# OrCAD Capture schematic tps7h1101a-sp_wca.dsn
size Custom; title: TPS7H1101A-SP 1.5-V to 7-V Input, 3-A; rev: C; note: Datasheet: SLVSDW6C   EVM User Guide: SLVU944B; note: Radiation-Hardened LDO Regulator
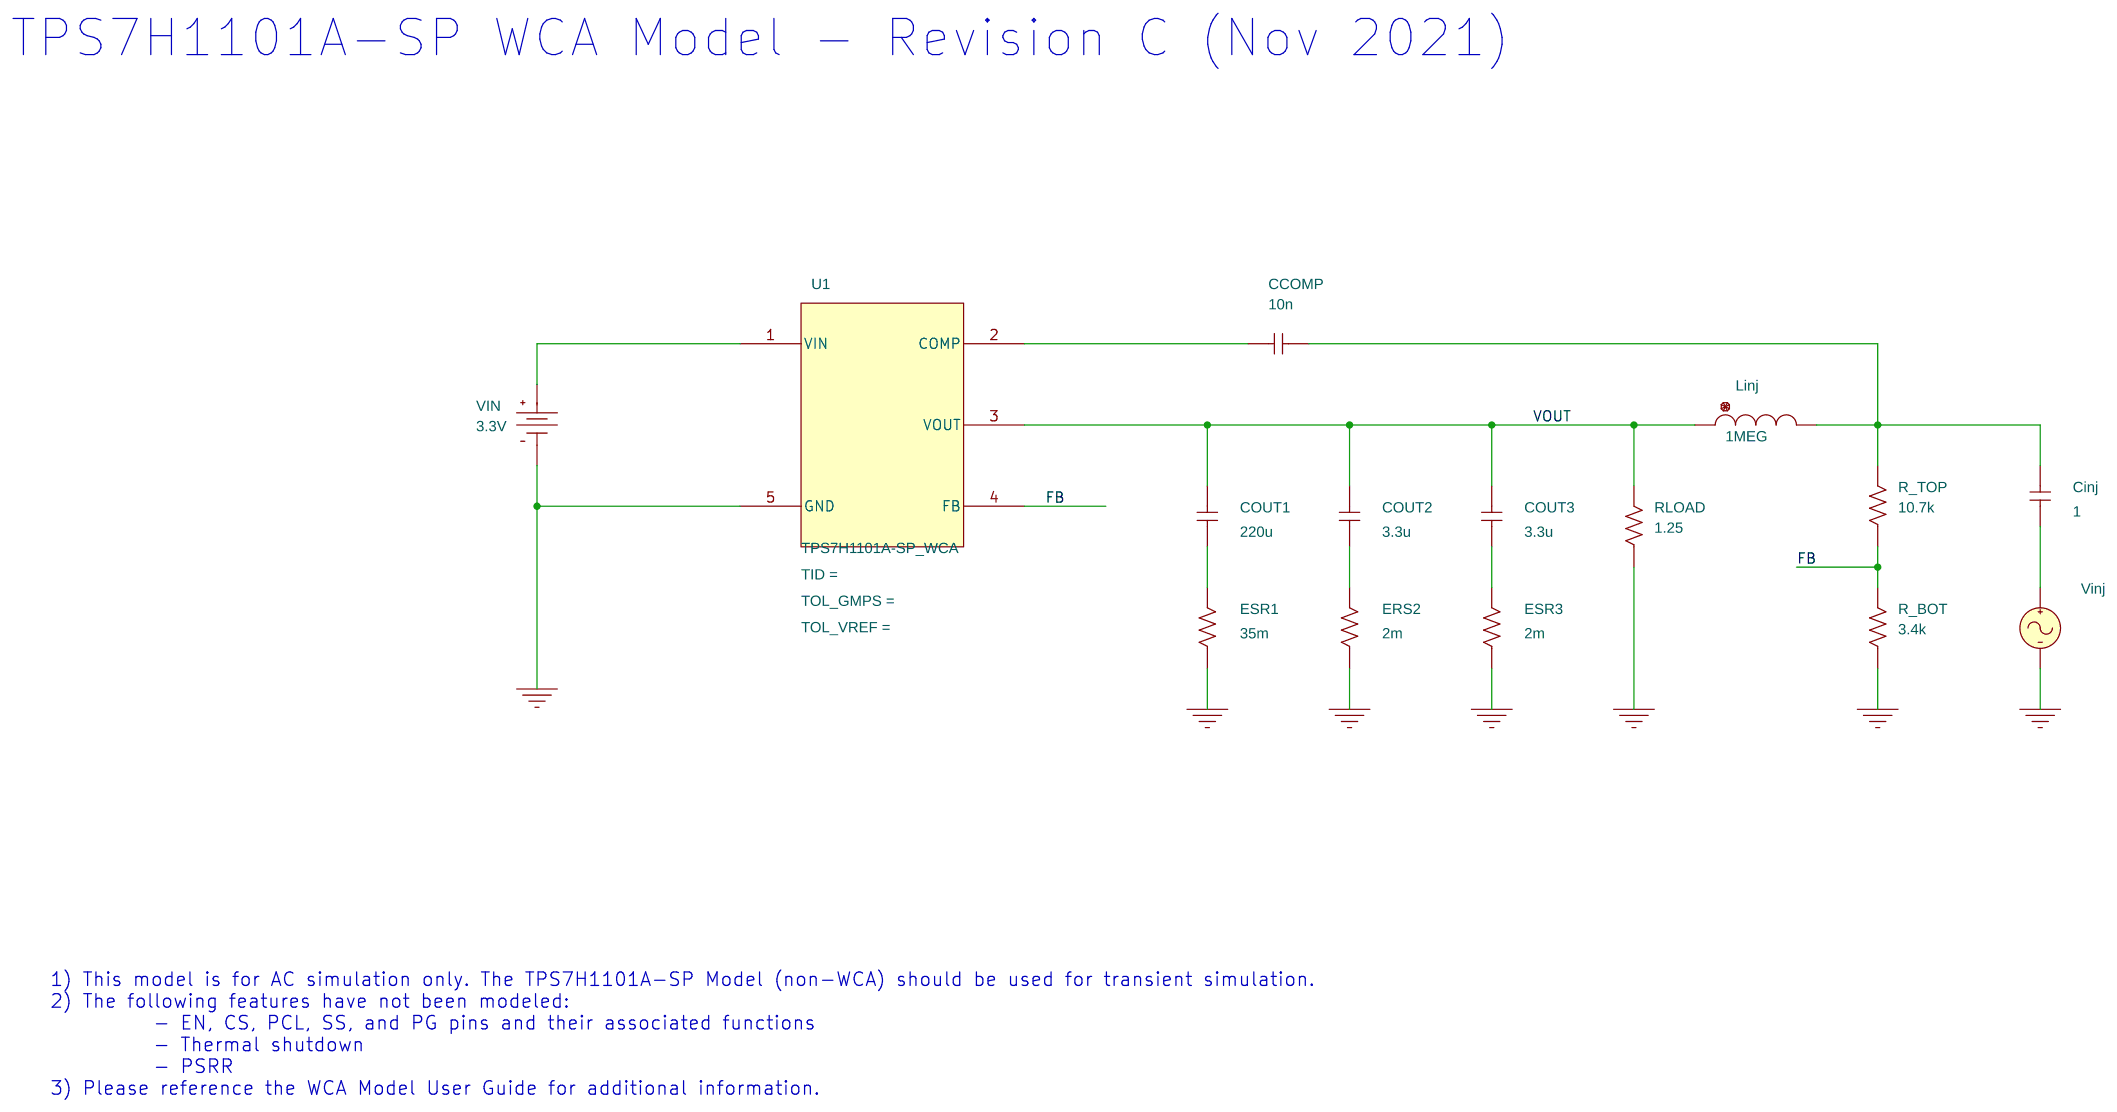
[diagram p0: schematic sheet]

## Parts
CCOMP  10n  [RAD/CK05]
Cinj  1  [RAD/CK05]
COUT1  220u  [RAD/CK05]
COUT2  3.3u  [RAD/CK05]
COUT3  3.3u  [RAD/CK05]
ERS2  2m  [AX/RC05]
ESR1  35m  [AX/RC05]
ESR3  2m  [AX/RC05]
Linj  1MEG  [DISC350x175LS200x100034]
R_BOT  3.4k  [AX/RC05]
R_TOP  10.7k  [AX/RC05]
RLOAD  1.25  [AX/RC05]
U1  TPS7H1101A-SP_WCA
VIN  VDC
Vinj  VAC

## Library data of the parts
CCOMP Cinj COUT1-COUT3 = C
ERS2 ESR1 ESR3 R_BOT R_TOP RLOAD = R
Linj = L
U1 = TPS7H1101A-SP_WCA_1: PSpiceTemplate: X^@REFDES  %VIN %COMP %VOUT %FB %GND @MODEL PARAMS: ?tid|tid=@tid||tid=0| ?tol_gmps|tol_gmps=@tol_gmps||tol_gmps=4.28| ?tol_vref|tol_vref=@tol_vref||tol_vref=0.41|
VIN = VDC: DC: 3.3V
Vinj = VAC

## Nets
0: ERS2.1 ESR1.1 ESR3.1 R_BOT.1 RLOAD.1 U1.5(GND) VIN.1(-) Vinj.2(-)
FB: R_BOT.2 R_TOP.1 U1.4(FB)
VOUT: COUT1.2 COUT2.2 COUT3.2 Linj.1 RLOAD.2 U1.3(VOUT)
N16626802: U1.1(VIN) VIN.0(+)
N16626812: CCOMP.1 U1.2(COMP)
N16626818: CCOMP.2 Cinj.2 Linj.2 R_TOP.2
N16627056: Cinj.1 Vinj.1(+)
N16627062: COUT1.1 ESR1.2
N16627068: COUT2.1 ERS2.2
N16627074: COUT3.1 ESR3.2

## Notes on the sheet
- TPS7H1101A-SP WCA Model - Revision C (Nov 2021)
- 1) This model is for AC simulation only. The TPS7H1101A-SP Model (non-WCA) should be used for transient simulation.
  2) The following features have not been modeled:
            - EN, CS, PCL, SS, and PG pins and their associated functions
            - Thermal shutdown
            - PSRR
  3) Please reference the WCA Model User Guide for additional information.
